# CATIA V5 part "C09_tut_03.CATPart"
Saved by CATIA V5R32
Part number: Part1
Bounding box of the stored display mesh (mm): x 0 to 224, y -87.701 to 88.93, z 0 to 67.047
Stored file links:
  D:\PROJECTS\Project 2022\CATIA V5 6R 2022\Resources\Tutorial Files\c09_catia_v5_6r2022_tut\C09_tut_03.CATPart
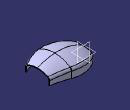
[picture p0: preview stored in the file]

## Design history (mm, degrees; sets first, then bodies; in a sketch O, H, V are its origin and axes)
Body1 (main body)
  Sketch1 on xy-plane, origin (0, 0, 0), H (1, 0, 0), V (0, 1, 0)
    arc A1 centre (95, -36.2404) radius 125 from (0, 45) to (139.6657, 80.5071) cw
    point P1 (95, -36.2404)
    point P2 (0, 45)
    arc A2 centre (289.027, 470.911) radius 418 from (139.6657, 80.5071) to (224, 58) ccw
    point P5 (224, 58)
    radius A1 = 125
    distance P2 H = 45
    distance P2 P5 H = 224
    radius A2 = 418
    distance P5 H = 58
    distance P1 V = 95
    coincidence: P2 V
    tangency: A2 A1
  Sketch2 on xy-plane, origin (0, 0, 0), H (1, 0, 0), V (0, 1, 0)
    axis line L1 (0, -58) -> (224, -58)
    point P1 (0, -58)
    point P2 (224, -58)
    arc A1 centre (112, 154.264) radius 240 from (0, -58) to (224, -58) ccw
    length L1 = 224
    radius A1 = 240
    distance H L1 = 58
    coincidence: P1 V
    horizontal: L1 H
  Sketch3 on zx-plane, origin (0, 0, 0), H (-1, 0, 0), V (0, 0, 1)
    arc A1 centre (-126.7082, -167.9142) radius 235 from (0, 30) to (-224, 46) ccw
    point P2 (0, 30)
    point P3 (-224, 46)
    axis line L1 (-224, 46) -> (-224, 0)
    point P4 (-224, 0)
    radius A1 = 235
    distance P2 H = 30
    length L1 = 46
    distance P2 P3 H = 224
    coincidence: P2 V, P4 H
    vertical: L1 V
  Sketch4 on yz-plane, origin (0, 0, 0), H (0, 1, 0), V (0, 0, 1)
    point P1 (45, 0)
    line L1 (45, 0) -> (45, 18.5632)
    point P3 (-58, 0)
    line L2 (-58, 0) -> (-58, 18.5632)
    arc A1 centre (-6.5, -89.8238) radius 120 from (-58, 18.5632) to (45, 18.5632) cw
    point P6 (0, 30)
    line L3 (45, 0) -> (-58, 0)
    reference projected point E1 (-58, 0) from Sketch2.P1
    reference projected point E2 (45, 0) from Sketch1.P2
    reference projected point E3 (0, 30) from Sketch3.P2
    construction line L4 (-58, 18.5632) -> (45, 18.5632)
    radius A1 = 120
    coincidence: P1 H, P3 H, A1 P6, P6 V, P3 E1, P1 E2, P6 E3
    vertical: L1 V, L2 V
    horizontal: L3 H, L4 H
  Plane1: type 3Points, Element1 Sketch2.P2, Element2 Sketch3.P3, Element3 Sketch1.P5
  Sketch5 on Plane1, origin (224, 0, 0), H (0, -1, 0), V (0, 0, 1)
    point P1 (-58, 0)
    line L1 (-58, 0) -> (58, 0)
    point P2 (58, 0)
    line L2 (58, 0) -> (58, 29.9794)
    arc A1 centre (0, -67) radius 113 from (58, 29.9794) to (-58, 29.9794) ccw
    point P5 (0, 46)
    line L3 (-58, 29.9794) -> (-58, 0)
    reference projected point E1 (-58, 0) from Sketch1.P5
    reference projected point E2 (58, 0) from Sketch2.P2
    reference projected point E3 (0, 46) from Sketch3.P3
    axis line L4 (58, 29.9794) -> (-58, 29.9794)
    radius A1 = 113
    coincidence: P1 H, A1 P5, P5 V, P1 E1, P2 E2, P5 E3
    horizontal: L1 H, L4 H
    vertical: L2 V, L3 V
  Loft1: solid, Sections (Sketch4; Sketch5), Guides (Sketch1; Sketch3; Sketch2)
  Fillet1: radius 25, on edge [face of Loft1 | face of Loft1] (x2)
  Fillet2: radius 15, on edge [face of Loft1 | face of Loft1]
  Shell1: ExtOffset 0, Face (face of Loft1; face of Loft1), IntOffset 3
